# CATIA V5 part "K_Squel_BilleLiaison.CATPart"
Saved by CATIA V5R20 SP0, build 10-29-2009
Part number: Squelette_bielle_liaison
Publications: "Point.6", "Plan.11", "Point.7", "Plan.16", "Plan.15", "Point.5"
Bounding box of the stored display mesh (mm): x -87 to -38, y 122.024 to 169.401, z -134.35 to -108.187
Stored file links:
  G:\Khaled_CFAO_2011\ST2M\ST2M_GR2\plakomicki\Khaled\CAD_ThinkMOTION\K_Squel_BilleLiaison.CATPart
  G:\Khaled_CFAO_2011\ST2M\ST2M_GR2\plakomicki\Khaled\CAD_ThinkMOTION\K_Squelette.CATProduct
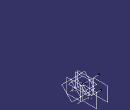
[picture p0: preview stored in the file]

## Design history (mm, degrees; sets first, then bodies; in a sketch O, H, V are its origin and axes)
External parameters (linked from other documents)
  External.entraxe_struct_bras = 87 mm
  External.entraxe_struct_balancier = 38 mm
Set1
  Point1: linked copy from another document
  Plane1: linked copy from another document
Set2
  Line1 "pivot_bielle_amortisseur": type PtDir, RefPoint Point1, Direction yz-plane, Start 0, End 49 {= External.entraxe_struct_bras -External.entraxe_struct_balancier}
  Point2: type OnCurve, Support Line1, Length 49
  Plane2: type OffsetPt, RefPlane xy-plane, RefPoint Point2
  Plane3: type Angle, RefPlane Plane2, Direction Line1, Angle -45
  Plane4: type Offset, RefPlane Plane3, Offset -37
  Point3: type OnPlane, Support Plane4, RefPoint Point2, H 0, V 0, Direction (-1, 0, 0)
  Line2: type PtPt, FirstPoint Point2, SecondPoint Point3
  Plane5: type OffsetPt, RefPlane yz-plane, RefPoint Point3
  Line3: type PtDir, RefPoint Point3, Direction Plane5, Start 0, End -33
  Plane6: type OffsetPt, RefPlane yz-plane, RefPoint vertex of Line3
  Plane7: type OffsetPt, RefPlane Plane6, RefPoint Point2
  Plane8: type Angle, RefPlane Plane3, Direction Line1, Angle -90
  Plane9: type Offset, RefPlane Plane8, Offset 30
  Point4: type OnPlane, Support Plane9, RefPoint Point2, H 0, V 0, Direction (-1, 0, 0)
  Line4: type PtPt, FirstPoint Point4, SecondPoint Point2
  Plane10: type OffsetPt, RefPlane yz-plane, RefPoint Point4
  Line5: type PtDir, RefPoint Point4, Direction Plane10, Start 0, End -33
  Plane11: type OffsetPt, RefPlane yz-plane, RefPoint vertex of Line5
Body1 (main body)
